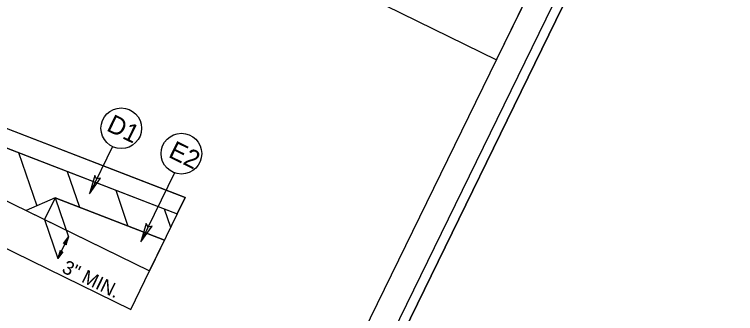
# Model space of a CAD drawing. Extents: x 1518247 to 1523638, y 635234 to 639927.
# Drawn here: x 1522580.9 to 1522921.3, y 638875 to 639016 of the extents above; entities that cross this region are included whole.
import ezdxf

# ---------------------------------------------------------------- set-up
doc = ezdxf.new("R2010")
doc.units = 0
for name, color, linetype in [('Default', 7, 'Continuous'), ('Prop Shade Light', 7, 'Continuous'), ('Sheet Plot Border Inside CELL', 7, 'Continuous'), ('Sheet Plot Border Outside CELL', 7, 'Continuous'), ('Sheet Typical CELL', 7, 'Continuous'), ('Typical Detail Wedge3 CELL', 7, 'Continuous'), ('Typical ID Circle CELL', 7, 'Continuous'), ('Typical Text ID Circle CELL', 7, 'Continuous')]:
    doc.layers.add(name, color=color, linetype=linetype)

msp = doc.modelspace()

# ---------------------------------------------------------------- linework, layer by layer
at = {"layer": 'Default'}
for points in [[(1522438.02, 638198.63), (1520925.25, 638938.49), (1521408.53, 639926.64), (1522921.3, 639186.78)], [(1522628.72, 639082.58), (1522808.42, 638994.69), (1522824.28, 639027.12), (1522644.58, 639115.01)]]:
    msp.add_lwpolyline(points, close=True, dxfattribs=at)
at = {"layer": 'Prop Shade Light'}
for points in [[(1522618.78, 638940.14), (1522616.26, 638931.5), (1522621.59, 638938.82), (1522619.68, 638938.5)], [(1522643.12, 638917.47), (1522640.6, 638908.82), (1522645.93, 638916.15), (1522644.02, 638915.82)]]:
    msp.add_lwpolyline(points, close=True, dxfattribs=at)
at = {"layer": 'Sheet Plot Border Inside CELL'}
msp.add_lwpolyline([(1522907.39, 639168.59), (1521410.35, 639900.76), (1520946.79, 638952.95), (1522443.84, 638220.77)], close=True, dxfattribs=at)
at = {"layer": 'Sheet Plot Border Outside CELL'}
msp.add_lwpolyline([(1522921.3, 639186.78), (1521408.53, 639926.64), (1520925.25, 638938.49), (1522438.02, 638198.63)], close=True, dxfattribs=at)
at = {"layer": 'Sheet Typical CELL'}
msp.add_lwpolyline([(1522895.04, 639171.79), (1521547.57, 639830.81), (1521086.25, 638887.58), (1522433.73, 638228.56)], close=True, dxfattribs=at)
at = {"layer": 'Typical Detail Wedge3 CELL'}
for p, q in [((1522368.03, 639043.05), (1522661.44, 638929.81)), ((1522363.04, 639032.84), (1522644.67, 638895.12)), ((1522354.31, 639014.64), (1522635.91, 638876.94)), ((1522458.22, 638998.99), (1522657.67, 638922.01)), ((1522582.8, 638950.89), (1522591.41, 638925.79)), ((1522605.75, 638942.04), (1522611.55, 638925.14)), ((1522628.7, 638933.19), (1522634.5, 638916.28)), ((1522600.11, 638929.55), (1522586.39, 638923.62)), ((1522600.11, 638929.55), (1522595.12, 638919.35)), ((1522600.11, 638929.55), (1522606.42, 638911.18)), ((1522600.11, 638929.55), (1522651.69, 638909.65)), ((1522661.44, 638929.81), (1522657.67, 638922.01)), ((1522661.44, 638929.81), (1522657.67, 638922.01)), ((1522651.65, 638924.33), (1522654.61, 638915.69)), ((1522657.67, 638922.01), (1522644.67, 638895.12)), ((1522595.12, 638919.35), (1522601.43, 638900.99)), ((1522601.43, 638900.99), (1522606.42, 638911.18)), ((1522635.91, 638876.94), (1522644.67, 638895.12))]:
    msp.add_line(p, q, dxfattribs=at)
for points in [[(1522368.03, 639043.05), (1522363.04, 639032.84), (1522442.95, 638993.76), (1522458.22, 638998.99), (1522657.67, 638922.01), (1522661.44, 638929.81)], [(1522600.11, 638929.55), (1522586.39, 638923.62), (1522644.67, 638895.12), (1522651.69, 638909.65)]]:
    msp.add_lwpolyline(points, close=True, dxfattribs=at)
for points in [[(1522604.1, 638908.01), (1522604.93, 638908.16), (1522605.32, 638907.41), (1522606.42, 638911.18), (1522605.22, 638907.62), (1522605.11, 638907.84), (1522606.42, 638911.18), (1522604.99, 638908.05), (1522604.93, 638908.16), (1522606.42, 638911.18), (1522604.7, 638908.11), (1522604.47, 638908.07), (1522606.42, 638911.18), (1522604.22, 638908.03), (1522604.1, 638908.01), (1522606.42, 638911.18)], [(1522603.73, 638904.15), (1522602.9, 638904), (1522602.51, 638904.75), (1522601.43, 638900.99), (1522602.62, 638904.54), (1522602.73, 638904.33), (1522601.43, 638900.99), (1522602.85, 638904.1), (1522602.9, 638904), (1522601.43, 638900.99), (1522603.14, 638904.04), (1522603.38, 638904.08), (1522601.43, 638900.99), (1522603.62, 638904.13), (1522603.73, 638904.15), (1522601.43, 638900.99)]]:
    msp.add_lwpolyline(points, dxfattribs=at)
at = {"layer": 'Typical ID Circle CELL'}
for p, q in [((1522627.13, 638953.76), (1522616.26, 638931.5)), ((1522656.49, 638941.37), (1522640.6, 638908.82))]:
    msp.add_line(p, q, dxfattribs=at)
for centre in [(1522631.33, 638962.37), (1522659.7, 638950.4)]:
    msp.add_circle(centre, 9.59, dxfattribs=at)

# ---------------------------------------------------------------- texts
at = {"layer": 'Typical Detail Wedge3 CELL'}
msp.add_text('3" MIN.', height=6.508, rotation=333.9377, dxfattribs=at).set_placement((1522602.83, 638894.67))
at = {"layer": 'Typical Text ID Circle CELL'}
for s, p in [('D1', (1522623.89, 638961.5)), ('E2', (1522653.1, 638949))]:
    msp.add_text(s, height=8.581, rotation=333.9793, dxfattribs=at).set_placement(p)

doc.saveas('drawing.dxf')
